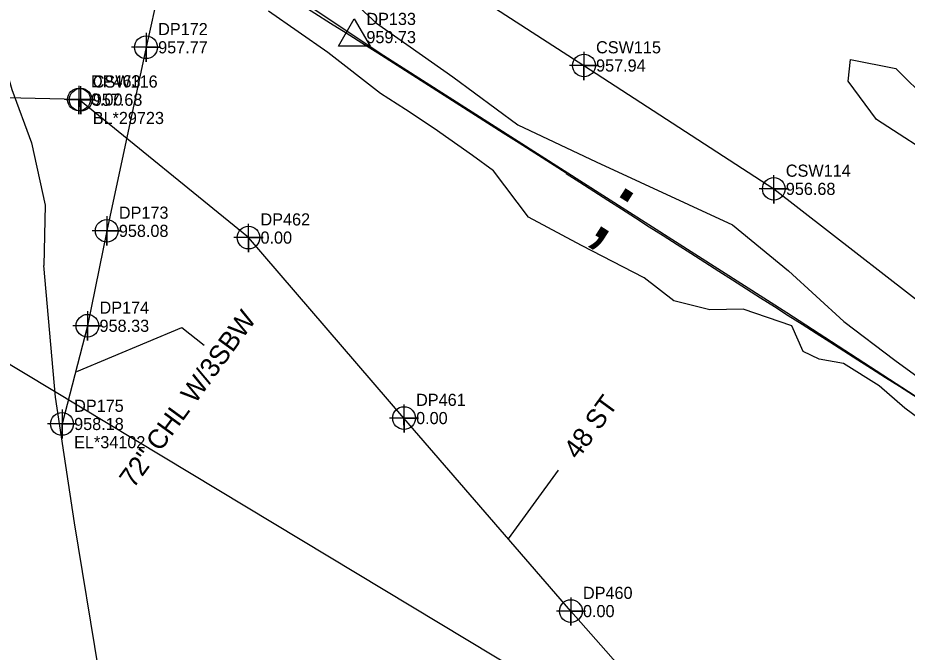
# Model space of a CAD drawing. Extents: x 1182322 to 1186765, y 572295 to 575411.
# Drawn here: x 1183900.4 to 1184083.8, y 573854 to 573984.8 of the extents above; entities that cross this region are included whole.
import ezdxf

# ---------------------------------------------------------------- set-up
doc = ezdxf.new("R2010")
doc.units = 0
for name, color, linetype in [('COGO Default Chain', 7, 'Continuous'), ('Exist Horizontal Alignment', 7, 'Continuous'), ('Exist Other Culture Fence Line', 7, 'Continuous'), ('Exist Other Culture Fence Line Cogo Comment', 7, 'Continuous'), ('Exist Other Culture Fence Line Cogo Elevation', 7, 'Continuous'), ('Exist Other Culture Fence Line Cogo Number', 7, 'Continuous'), ('Exist Other Culture Fence Line Cogo Point CELL', 7, 'Continuous'), ('Exist Other Culture Fence Line Leader', 7, 'Continuous'), ('Exist Other Culture Fence Line Text', 7, 'Continuous'), ('Exist Right of Way Control of Access CA Symbol CELL', 7, 'Continuous'), ('Exist Right of Way Line', 7, 'Continuous'), ('Exist Right of Way Monument CELL', 7, 'Continuous'), ('Exist Right of Way Monument Cogo Elevation', 7, 'Continuous'), ('Exist Right of Way Monument Cogo Number', 7, 'Continuous'), ('Exist Roads Soil', 7, 'Continuous'), ('Exist Utilities Telephone UG Conduit SUE LOS B', 7, 'Continuous'), ('Exist Utilities Telephone UG Conduit SUE LOS B Cogo Comment', 7, 'Continuous'), ('Exist Utilities Telephone UG Conduit SUE LOS B Cogo Elevation', 7, 'Continuous'), ('Exist Utilities Telephone UG Conduit SUE LOS B Cogo Number', 7, 'Continuous'), ('Exist Utilities Telephone UG Conduit SUE LOS B Cogo Point CELL', 7, 'Continuous'), ('Exist Utilities Telephone UG Conduit SUE LOS B Leader', 7, 'Continuous'), ('Exist Utilities Telephone UG Conduit SUE LOS B Text', 7, 'Continuous'), ('Exist Vegetation Woods Line', 7, 'Continuous'), ('Sheet Layout Plan Border', 7, 'Continuous')]:
    doc.layers.add(name, color=color, linetype=linetype)

msp = doc.modelspace()

# ---------------------------------------------------------------- linework, layer by layer
at = {"layer": 'COGO Default Chain'}
msp.add_arc((1195941.73, 592569.89), 22022.71, 237.351741, 237.915207, dxfattribs=at)
at = {"layer": 'Exist Horizontal Alignment'}
msp.add_arc((1195941.73, 592569.89), 22022.71, 237.351741, 237.915207, dxfattribs=at)
at = {"layer": 'Exist Other Culture Fence Line'}
for points in [[(1183932.23, 574002.98), (1183926.85, 573978.68), (1183918.75, 573940.86), (1183914.77, 573921.3), (1183909.53, 573901.07)], [(1184129.53, 573878.39), (1184114.9, 573888.31), (1184094.64, 573900.8), (1184058.94, 573923.99), (1183975.11, 573977.38), (1183956.27, 573990.02)]]:
    msp.add_lwpolyline(points, dxfattribs=at)
at = {"layer": 'Exist Other Culture Fence Line Cogo Point CELL'}
for points in [[(1183926.85, 573981.68), (1183926.85, 573975.68), (1183926.85, 573978.68), (1183929.85, 573978.68), (1183923.85, 573978.68)], [(1183918.75, 573943.86), (1183918.75, 573937.86), (1183918.75, 573940.86), (1183921.75, 573940.86), (1183915.75, 573940.86)], [(1183914.77, 573924.3), (1183914.77, 573918.3), (1183914.77, 573921.3), (1183917.77, 573921.3), (1183911.77, 573921.3)], [(1183909.53, 573904.07), (1183909.53, 573898.07), (1183909.53, 573901.07), (1183912.53, 573901.07), (1183906.53, 573901.07)]]:
    msp.add_lwpolyline(points, dxfattribs=at)
for centre in [(1183926.85, 573978.68), (1183918.75, 573940.86), (1183914.77, 573921.3), (1183909.53, 573901.07)]:
    msp.add_circle(centre, 2.34, dxfattribs=at)
at = {"layer": 'Exist Other Culture Fence Line Leader'}
msp.add_lwpolyline([(1183912.56, 573911.85), (1183934.23, 573920.94), (1183938.82, 573917.28)], dxfattribs=at)
at = {"layer": 'Exist Right of Way Control of Access CA Symbol CELL'}
msp.add_line((1184028.28, 573943.22), (1184028.28, 573943.22), dxfattribs=at)
at = {"layer": 'Exist Right of Way Line'}
for centre, radius, start, end in [((1179021.49, 566161.49), 9253.26, 57.351741, 58.1119), ((1195941.73, 592569.89), 22110.71, 237.351741, 237.915207)]:
    msp.add_arc(centre, radius, start, end, dxfattribs=at)
at = {"layer": 'Exist Right of Way Monument CELL'}
msp.add_line((1183969.78, 573980.78), (1183969.78, 573980.78), dxfattribs=at)
msp.add_lwpolyline([(1183966.53, 573978.89), (1183969.78, 573984.53), (1183973.03, 573978.89)], close=True, dxfattribs=at)
at = {"layer": 'Exist Roads Soil'}
for points in [[(1183744.64, 574103.16), (1183762.37, 574094.18), (1183779.88, 574084.39), (1183794.39, 574076.82), (1183806.99, 574069.39), (1183821.88, 574059.42), (1183834.45, 574050.34), (1183846.93, 574040.04), (1183857.42, 574030.99), (1183872.81, 574016.3), (1183883.86, 574004.18), (1183890.16, 573994.07), (1183895.44, 573982.91), (1183899.22, 573969.98), (1183903.21, 573958.97), (1183906.09, 573946.12), (1183905.79, 573933.74)], [(1183918.94, 573744.99), (1183920.27, 573780.65), (1183919.33, 573820.36), (1183917.15, 573850.21), (1183912.11, 573880.71), (1183908.2, 573906.6), (1183905.79, 573933.74)]]:
    msp.add_lwpolyline(points, dxfattribs=at)
at = {"layer": 'Exist Utilities Telephone UG Conduit SUE LOS B'}
for points in [[(1183184.2, 574290.24), (1183230.46, 574277.8), (1183276.74, 574264.86), (1183322.88, 574252.13), (1183369.36, 574239.84), (1183416.41, 574227.82), (1183461.9, 574217.61), (1183507.97, 574205.1), (1183555.78, 574190.97), (1183600.29, 574174.7), (1183642.38, 574158.78), (1183685.83, 574141.54), (1183729.44, 574124.53), (1183772.61, 574105.48), (1183815.48, 574084.72), (1183856.9, 574064.89), (1183910.26, 574040.72), (1183938.65, 574025.64), (1184017.13, 573974.93), (1184056.25, 573949.51), (1184095.95, 573918.75), (1184120.25, 573896.12), (1184153.18, 573876.37), (1184177.6, 573863.32)], [(1183913, 573967.93), (1183865.04, 573969.03), (1183815.77, 573969.72), (1183770.48, 573970.3)], [(1184210.63, 573717.89), (1184181.04, 573731.42), (1184150.69, 573741.38), (1184111.86, 573755.94), (1184075.03, 573792.9), (1184045.3, 573827.54), (1184014.43, 573862.52), (1183980.03, 573902.29), (1183947.95, 573939.47), (1183913, 573967.93)]]:
    msp.add_lwpolyline(points, dxfattribs=at)
at = {"layer": 'Exist Utilities Telephone UG Conduit SUE LOS B Cogo Point CELL'}
for points in [[(1184017.11, 573977.75), (1184017.14, 573971.93), (1184017.13, 573974.93), (1184020.14, 573974.93), (1184014.14, 573974.93)], [(1183912.98, 573970.74), (1183913.02, 573964.93), (1183913, 573967.93), (1183916.02, 573967.93), (1183910.02, 573967.93)], [(1183913.35, 573970.69), (1183913.39, 573964.87), (1183913.37, 573967.87), (1183916.39, 573967.87), (1183910.39, 573967.87)], [(1184056.24, 573952.33), (1184056.27, 573946.51), (1184056.25, 573949.51), (1184059.27, 573949.51), (1184053.27, 573949.51)], [(1183947.93, 573942.29), (1183947.97, 573936.47), (1183947.95, 573939.47), (1183950.97, 573939.47), (1183944.97, 573939.47)], [(1183980.01, 573905.11), (1183980.04, 573899.29), (1183980.03, 573902.29), (1183983.04, 573902.29), (1183977.04, 573902.29)], [(1184014.41, 573865.34), (1184014.44, 573859.52), (1184014.43, 573862.52), (1184017.44, 573862.52), (1184011.44, 573862.52)]]:
    msp.add_lwpolyline(points, dxfattribs=at)
for centre in [(1184017.14, 573974.93), (1183913.02, 573967.93), (1183913.39, 573967.87), (1184056.27, 573949.51), (1183947.97, 573939.47), (1183980.04, 573902.29), (1184014.44, 573862.52)]:
    msp.add_circle(centre, 2.34, dxfattribs=at)
at = {"layer": 'Exist Utilities Telephone UG Conduit SUE LOS B Leader'}
msp.add_line((1184001.57, 573877.39), (1184011.87, 573891.52), dxfattribs=at)
at = {"layer": 'Exist Vegetation Woods Line'}
for points in [[(1183964.85, 573992.46), (1183974.34, 573983.65), (1183990.11, 573972.59), (1184003.49, 573962.7), (1184019.65, 573955.11), (1184047.79, 573942.09), (1184059.32, 573932.64), (1184070.71, 573922.15), (1184081.21, 573914.19), (1184097.46, 573902.41)], [(1184088.01, 573900.83), (1184083.28, 573904.35), (1184077.96, 573908.96), (1184070.65, 573913.53), (1184065.65, 573914.39), (1184062.32, 573916.01), (1184059.97, 573921.29), (1184049.98, 573924.72), (1184043.07, 573924.58), (1184035.68, 573926.45), (1184029.53, 573931.19), (1184016.6, 573937.86), (1184005.69, 573943.71), (1183998.48, 573953.21), (1183994.19, 573956.41), (1183986.28, 573961.95), (1183980.34, 573965.88), (1183975.22, 573969.18), (1183964.35, 573977.64), (1183952.09, 573986.12)], [(1184091.28, 573954.86), (1184077.46, 573963.8), (1184071.62, 573971.68), (1184072.05, 573976.13), (1184081.45, 573974.29), (1184088.2, 573967.55)]]:
    msp.add_lwpolyline(points, dxfattribs=at)
at = {"layer": 'Sheet Layout Plan Border'}
msp.add_line((1184011.14, 573845.69), (1183494.54, 574156.56), dxfattribs=at)

# ---------------------------------------------------------------- texts
at = {"layer": 'Exist Other Culture Fence Line Cogo Comment'}
msp.add_text('EL*34102', height=2.5, dxfattribs=at).set_placement((1183912.03, 573896.07))
at = {"layer": 'Exist Other Culture Fence Line Cogo Elevation'}
for s, p in [('957.77', (1183929.35, 573977.43)), ('958.08', (1183921.25, 573939.61)), ('958.33', (1183917.27, 573920.05)), ('958.18', (1183912.03, 573899.82))]:
    msp.add_text(s, height=2.5, dxfattribs=at).set_placement(p)
at = {"layer": 'Exist Other Culture Fence Line Cogo Number'}
for s, p in [('DP172', (1183929.35, 573981.18)), ('DP173', (1183921.25, 573943.36)), ('DP174', (1183917.27, 573923.8)), ('DP175', (1183912.03, 573903.57))]:
    msp.add_text(s, height=2.5, dxfattribs=at).set_placement(p)
at = {"layer": 'Exist Other Culture Fence Line Text'}
msp.add_text('72" CHL W/3SBW', height=4, rotation=53.9157, dxfattribs=at).set_placement((1183924.28, 573887.66))
at = {"layer": 'Exist Right of Way Control of Access CA Symbol CELL'}
msp.add_text(';', height=15, rotation=327.3974, dxfattribs=at).set_placement((1184017.92, 573940.94))
at = {"layer": 'Exist Right of Way Monument Cogo Elevation'}
msp.add_text('959.73', height=2.5, dxfattribs=at).set_placement((1183972.28, 573979.53))
at = {"layer": 'Exist Right of Way Monument Cogo Number'}
msp.add_text('DP133', height=2.5, dxfattribs=at).set_placement((1183972.28, 573983.28))
at = {"layer": 'Exist Utilities Telephone UG Conduit SUE LOS B Cogo Comment'}
msp.add_text('BL*29723', height=2.5, dxfattribs=at).set_placement((1183915.87, 573962.87))
at = {"layer": 'Exist Utilities Telephone UG Conduit SUE LOS B Cogo Elevation'}
for s, p in [('957.94', (1184019.63, 573973.68)), ('0.00', (1183915.5, 573966.68)), ('957.68', (1183915.87, 573966.62)), ('956.68', (1184058.75, 573948.26)), ('0.00', (1183950.45, 573938.22)), ('0.00', (1183982.53, 573901.04)), ('0.00', (1184016.93, 573861.27))]:
    msp.add_text(s, height=2.5, dxfattribs=at).set_placement(p)
at = {"layer": 'Exist Utilities Telephone UG Conduit SUE LOS B Cogo Number'}
for s, p in [('CSW115', (1184019.63, 573977.43)), ('DP463', (1183915.5, 573970.43)), ('CSW116', (1183915.87, 573970.37)), ('CSW114', (1184058.75, 573952.01)), ('DP462', (1183950.45, 573941.97)), ('DP461', (1183982.53, 573904.79)), ('DP460', (1184016.93, 573865.02))]:
    msp.add_text(s, height=2.5, dxfattribs=at).set_placement(p)
at = {"layer": 'Exist Utilities Telephone UG Conduit SUE LOS B Text'}
msp.add_text('48 ST', height=4, rotation=53.9157, dxfattribs=at).set_placement((1184015.88, 573893.55))

doc.saveas('drawing.dxf')
